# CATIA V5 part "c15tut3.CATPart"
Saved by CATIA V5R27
Part number: Part1
Bounding box of the stored display mesh (mm): x -75 to 75, y -40 to 40, z 0 to 5
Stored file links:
  E:\_Deepak\2017_Deepak\CATIA\Resources\Tutorial Files\Tutorials\c15_catia_v5_6r2016_tut\c15tut3.CATPart
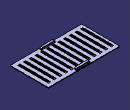
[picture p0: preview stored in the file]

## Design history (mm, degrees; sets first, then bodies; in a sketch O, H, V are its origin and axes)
SheetMetalParameters1: Thickness 1, BendRadius 2, KFactor 0.400515 {= log(min(100,max(20*SheetMetalParameters1.BendRadius,SheetMetalParameters1.Thickness)/SheetMetalParameters1.Thickness))/log(100)/2}, ReliefRadialLength 1, ReliefAxialLength 2, MinimumBendRadius 0
Body1 (main body)
  Sketch1 on xy-plane, origin (0, 0, 0), H (1, 0, 0), V (0, 1, 0)
    line L1 (75, 40) -> (75, -40)
    line L2 (75, -40) -> (-75, -40)
    line L3 (-75, -40) -> (-75, 40)
    line L4 (-75, 40) -> (75, 40)
    length L4 = 150
    length L1 = 80
    vertical: L1 V, L3 V
    horizontal: L2 H, L4 H
    equidistance: L1 L3 O, L2 L4 O
  Wall1: Thickness 1, Profile Sketch1
  Sketch2 on face of Wall1, origin (0, 0, 0), H (1, 0, 0), V (0, 1, 0)
    line L1 (64.5, 30) -> (67, 30)
    line L2 (67, 30) -> (67, -30)
    line L3 (67, -30) -> (64.5, -30)
    line L4 (64.5, -30) -> (64.5, 30)
    reference projected line E1 (75, 40) -> (75, -40) from edge [face of Wall1 | face of Wall1]
    reference projected line E2 (-75, 40) -> (75, 40) from edge [face of Wall1 | face of Wall1]
    length L2 = 60
    distance L2 L4 = 2.5
    distance E1 L2 = 8
    distance L1 E2 = 10
    horizontal: L1 H, L3 H
    vertical: L2 V, L4 V
  d_Stamp1: NewRoot_AttribNormalisation "No Standard", Stamp_FilletRadius 2
  RectPattern1: of d_Stamp1, direction 1 instances 12, spacing 12, along face of Wall1 reversed
  Sketch3 on face of Wall1, origin (0, 0, 0), H (1, 0, 0), V (0, -1, 0)
    point P1 (0, 36.5)
    reference projected line E1 (75, 40) -> (75, -40) from edge [face of Wall1 | face of Wall1]
    reference projected line E2 (-75, 40) -> (75, 40) from edge [face of Wall1 | face of Wall1]
    distance P1 E1 = 75
    distance P1 E2 = 3.5
  Sketch4 on face of Wall1, origin (0, -36.5, 0), H (1, 0, 0), V (0, 1, 0)
    point P1 (0, 0)
    reference projected point E1 (0, 0) from Sketch3.P1
    coincidence: E1 P1
  d_Stamp2: NewRoot_AttribNormalisation "No Standard", Stamp_FilletRadius 0.5
  SHM_Mirror1: MirroringPlane zx-plane, ObjectToMirror d_Stamp2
